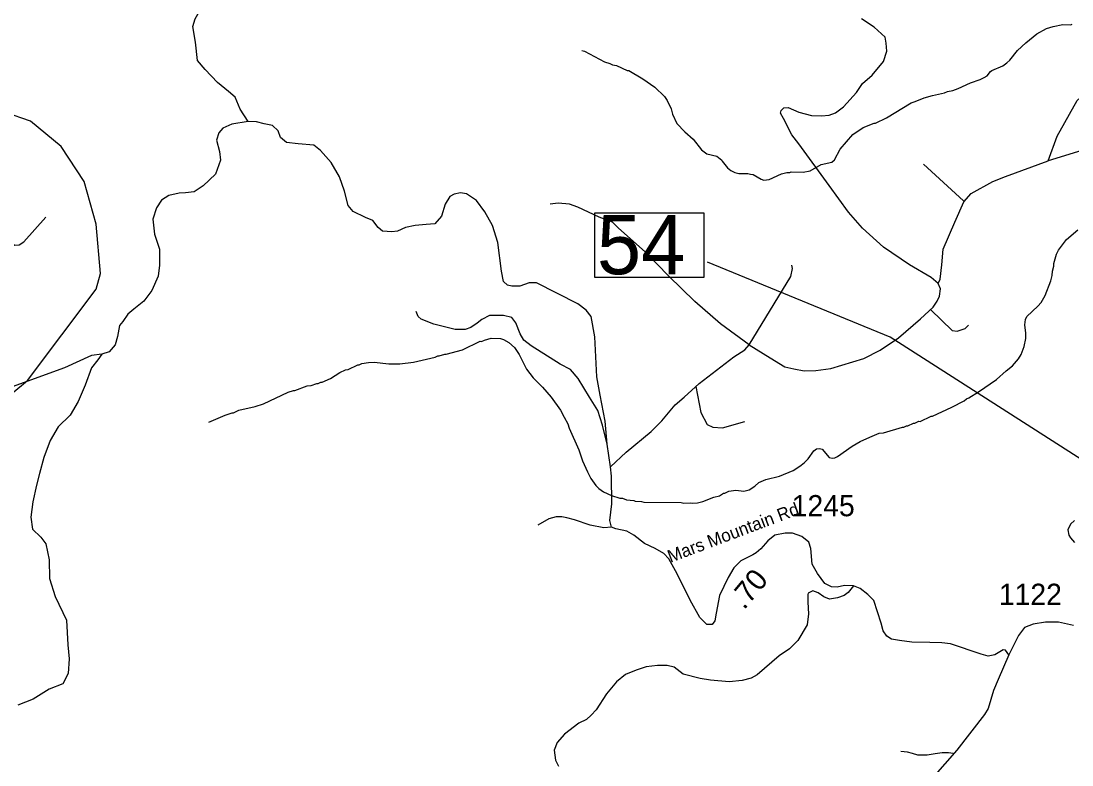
# Model space of a CAD drawing. Extents: x 1248089 to 1457196, y 820910 to 988753.
# Drawn here: x 1318874 to 1325079, y 852699 to 857095 of the extents above; entities that cross this region are included whole.
import ezdxf

# ---------------------------------------------------------------- set-up
doc = ezdxf.new("R2010")
doc.units = 0
for name, color, linetype in [('Exist Hydrographic Misc Water Feature', 7, 'Continuous'), ('Exist Road Non-System Type 51', 7, 'Continuous'), ('Exist Road Secondary Structure Standard Bridge Number Label', 7, 'Continuous'), ('Exist Road Secondary Type 51 Attributed', 7, 'Continuous'), ('Exist Road Secondary Type 51 Label', 7, 'Continuous'), ('Prop GRAU CAT1 Cell', 7, 'Continuous'), ('Prop Lane Lines', 7, 'Continuous')]:
    doc.layers.add(name, color=color, linetype=linetype)

msp = doc.modelspace()

# ---------------------------------------------------------------- linework, layer by layer
at = {"layer": 'Exist Hydrographic Misc Water Feature'}
for points in [[(1324152.8, 856618.6), (1324206.2, 856640.8), (1324254.5, 856655.6), (1324326.9, 856669.9), (1324343, 856677.6), (1324375.2, 856684.8), (1324407.5, 856696), (1324480.3, 856730.3), (1324536.6, 856749), (1324560.9, 856760.4), (1324577.1, 856770), (1324597.8, 856795.6), (1324605.9, 856801.4), (1324670.5, 856829.9), (1324694.9, 856847.3), (1324711.2, 856862.9), (1324756.6, 856919.8), (1324805.6, 856966.6), (1324870.8, 857019.1), (1324927.5, 857049.8), (1324967.8, 857062.9), (1325024.1, 857073.5), (1325072, 857072.4), (1325080.1, 857076.2)], [(1322184.3, 856920.1), (1322200.2, 856915.7), (1322318.8, 856853), (1322350.6, 856844.2), (1322366.4, 856835.9), (1322390.4, 856831.3), (1322453.6, 856801.8), (1322461.6, 856801.6), (1322544.6, 856753.7), (1322615.4, 856704.1), (1322672.2, 856648.7), (1322689.6, 856624.3), (1322712.6, 856575.8), (1322719.9, 856543.6), (1322746.6, 856489), (1322793.5, 856439.9), (1322842.5, 856396.8), (1322891.1, 856333.6), (1322922.6, 856310.9), (1322982.2, 856295.5), (1323011.8, 856272.8), (1323013.6, 856266.8), (1323044.7, 856228), (1323064.4, 856211.6), (1323088.1, 856199), (1323111.9, 856194.5), (1323166, 856193.2), (1323179.8, 856188.9), (1323195.8, 856188.5), (1323243.2, 856159.4), (1323259.1, 856155), (1323291.2, 856158.3), (1323364, 856192.6), (1323396.1, 856199.8), (1323412.1, 856199.4), (1323420.2, 856203.3), (1323492.2, 856201.6), (1323532.3, 856208.6), (1323597.2, 856247.1), (1323661.6, 856261.6), (1323675.8, 856275.3), (1323709.3, 856338.5), (1323785.2, 856424.7), (1323846.1, 856465.2), (1323910.8, 856491.7), (1323918.8, 856491.5), (1323983.5, 856522), (1324129.5, 856610.6), (1324152.8, 856618.6)], [(1318656.8, 854759.6), (1318911.8, 854971.1), (1319316.8, 855511.2), (1319343.8, 855602.6), (1319316.8, 855895.3), (1319247.8, 856146.2), (1319110.8, 856352.5), (1318930.8, 856503.8), (1318632.7, 856605)], [(1323941.3, 854659.3), (1323965.4, 854662.7), (1324078.1, 854696.1), (1324086.1, 854695.9), (1324102.3, 854703.5), (1324110.3, 854703.3), (1324142.6, 854718.5), (1324150.6, 854718.4), (1324174.9, 854729.8), (1324182.9, 854729.6), (1324247.6, 854760.1), (1324255.6, 854759.9), (1324368.8, 854813.2), (1324441.7, 854851.5), (1324456, 854863.2), (1324470.1, 854868.9), (1324526.9, 854903.5), (1324632.6, 854977), (1324689.7, 855027.7), (1324728.4, 855056.8), (1324763.3, 855099.9), (1324777.9, 855123.6), (1324797, 855171.1), (1324806.1, 855218.9), (1324806.8, 855250.9), (1324799.8, 855299.1), (1324804.5, 855330.9), (1324813, 855348.7), (1324876.4, 855409.3), (1324896.9, 855432.7), (1324919.8, 855472.2), (1324953.8, 855559.4), (1324962.5, 855591.2), (1324963.1, 855617.2), (1324971.8, 855647), (1324972.2, 855663), (1324987.4, 855716.6), (1324999.9, 855740.3), (1325047.3, 855803.2), (1325112.6, 855861.7)], [(1319982.4, 854724.1), (1320079.3, 854765.8), (1320119.7, 854780.9), (1320127.7, 854780.7), (1320160, 854795.9), (1320256.6, 854817.6), (1320304.9, 854832.5), (1320450.5, 854901.1), (1320482.8, 854912.3), (1320490.8, 854912.2), (1320563.4, 854938.5), (1320587.4, 854941.9), (1320619.6, 854953.1), (1320627.6, 854952.9), (1320643.8, 854960.6), (1320651.8, 854960.4), (1320700.3, 854983.2), (1320757.1, 855017.9), (1320789.5, 855033.1), (1320805.6, 855036.7), (1320862.2, 855063.4), (1320870.2, 855063.2), (1320886.3, 855070.8), (1320926.5, 855077.9), (1320958.6, 855079.1), (1321046.4, 855069.1), (1321110.3, 855069.6), (1321190.6, 855079.7), (1321319.3, 855108.7), (1321335.4, 855116.3), (1321343.4, 855116.1), (1321375.7, 855127.4), (1321383.7, 855127.2), (1321480.2, 855152.9), (1321585.4, 855202.4), (1321593.4, 855202.3), (1321609.5, 855209.9), (1321649.8, 855220.9), (1321705.8, 855219.6), (1321721.7, 855213.2), (1321753.3, 855194.5), (1321786.6, 855165.7), (1321815.7, 855125.1), (1321857.7, 855038.1), (1321898.5, 854987.1), (1321953.3, 854931.9), (1322003.9, 854872.7), (1322058.2, 854795.4), (1322080.7, 854754.6), (1322102.4, 854714.4), (1322109.9, 854690.3), (1322167, 854560.9), (1322189.5, 854496.4), (1322218, 854431.7), (1322239.1, 854391.2), (1322268.2, 854350.6), (1322285.8, 854332.2), (1322313.4, 854313.5), (1322360.8, 854292.4), (1322408.5, 854275.3), (1322424.5, 854274.9), (1322448.3, 854266.4), (1322492.2, 854261.3), (1322500.1, 854257.1), (1322538.1, 854256.3), (1322551.9, 854252), (1322772, 854250.8), (1322787.9, 854246.4), (1322827.9, 854247.5), (1322835.8, 854245.3), (1322867.9, 854248.5), (1322900.1, 854255.8), (1322964.7, 854282.2), (1322996.9, 854289.5), (1323021.2, 854304.9), (1323029.2, 854304.8), (1323053.5, 854316.2), (1323093.6, 854323.2), (1323141.6, 854318.1), (1323173.7, 854325.4), (1323206.2, 854346.6), (1323230.7, 854368), (1323271.1, 854387), (1323351.5, 854405.2), (1323432.3, 854439.3), (1323472.8, 854464.3), (1323497.3, 854483.7), (1323521.8, 854509.1), (1323555, 854556.4), (1323571.3, 854568), (1323587.3, 854569.6), (1323603.1, 854565.2), (1323646.1, 854516.3), (1323662, 854511.9), (1323678, 854513.5), (1323694.2, 854521.1), (1323781.5, 854583.1), (1323828.2, 854610), (1323884.8, 854636.6), (1323941.3, 854659.3)]]:
    msp.add_lwpolyline(points, dxfattribs=at)
at = {"layer": 'Exist Road Non-System Type 51'}
msp.add_line((1324438, 856032.4), (1324201.2, 856249.4), dxfattribs=at)
for points in [[(1320215.8, 856501.4), (1320167.2, 856574.7), (1320137.4, 856645.1), (1320099.5, 856677.6), (1320034.6, 856731.8), (1319961.5, 856807.6), (1319915.5, 856861.8), (1319904.7, 856970.1), (1319888.5, 857062.2), (1319902, 857108.2), (1319934.5, 857162.4), (1319948, 857224.7), (1319956.1, 857295.1), (1319939.9, 857370.9), (1319902, 857398), (1319856, 857406.1), (1319804.6, 857406.1), (1319753.1, 857403.4), (1319718, 857422.4), (1319625.9, 857528)], [(1324288.6, 855544), (1324248.1, 855579.7), (1324119.9, 855654.5), (1323965, 855758.8), (1323842.1, 855871), (1323759.3, 855964.6), (1323644.5, 856122.3), (1323465.5, 856368.2), (1323425.4, 856421.6), (1323374.7, 856517.9), (1323358.7, 856549.9), (1323361.3, 856566), (1323377.4, 856582), (1323404.1, 856584.7), (1323465.5, 856555.3), (1323540.3, 856536.6), (1323599.1, 856533.9), (1323644.5, 856539.3), (1323681.9, 856552.6), (1323729.9, 856587.4), (1323807.4, 856672.9), (1323842.1, 856726.4), (1323898.2, 856774.5), (1323965, 856854.7), (1323986.4, 856916.1), (1323981, 856964.3), (1323975.7, 856999), (1323911.6, 857057.8), (1323837, 857107)], [(1324938.4, 856267.8), (1324991.8, 856414.7), (1325108.6, 856625), (1325165.3, 856675.1), (1325358.8, 856775.2), (1325412.2, 856798.6), (1325475.5, 856785.3), (1325462.2, 856681.8), (1325422.2, 856581.6), (1325305.4, 856471.4)], [(1320215.8, 856501.4), (1320119.2, 856485.3), (1320065.5, 856461.1), (1320041.3, 856434.2), (1320027.9, 856391.3), (1320046.7, 856324.1), (1320052.1, 856273.1), (1320022.5, 856189.8), (1319950.1, 856120), (1319896.4, 856085.1), (1319845.4, 856079.7), (1319807.8, 856077), (1319746.1, 856063.6), (1319703.1, 856036.7), (1319673.6, 855991), (1319652.1, 855923.9), (1319662.9, 855835.2), (1319692.4, 855746.6), (1319692.4, 855652.6), (1319684.3, 855588.1), (1319646.8, 855502.2), (1319598.5, 855440.4), (1319539.4, 855392), (1319504.5, 855362.5), (1319475, 855319.5), (1319456.2, 855295.4), (1319442.8, 855230.9), (1319429.4, 855182.5), (1319394.5, 855139.6), (1319351.5, 855126.1)], [(1320983.4, 855875.5), (1320951.2, 855915.8), (1320908.3, 855934.6), (1320835.8, 855969.6), (1320806.3, 856004.5), (1320784.8, 856090.4), (1320755.3, 856173.7), (1320704.3, 856259.6), (1320642.6, 856329.5), (1320602.3, 856361.7), (1320511, 856369.8), (1320441.3, 856377.8), (1320406.4, 856407.4), (1320392.9, 856445), (1320358, 856477.2), (1320309.7, 856488), (1320264.1, 856498.7), (1320215.8, 856501.4)], [(1325305.4, 856471.4), (1325178.6, 856347.9), (1325111.9, 856321.2), (1324938.4, 856267.8)], [(1324288.6, 855544), (1324301.5, 855569.6), (1324309.5, 855655.1), (1324317.5, 855746), (1324386.9, 855906.4), (1324440.4, 856026.7), (1324483.1, 856074.8), (1324611.3, 856147), (1324686.1, 856176.4), (1324938.4, 856267.8)], [(1322334.6, 854595.3), (1322322.8, 854731.3), (1322293.3, 854884.4), (1322274.5, 854991.8), (1322261.1, 855228.2), (1322239.6, 855349.1), (1322210.1, 855386.7), (1322161.7, 855424.3), (1321917.5, 855547.8), (1321874.6, 855547.8), (1321818.2, 855529), (1321772.6, 855529), (1321745.7, 855534.4), (1321721.6, 855555.9), (1321710.8, 855617.7), (1321689.4, 855786.9), (1321657.1, 855886.3), (1321611.5, 855966.9), (1321563.2, 856034), (1321504.1, 856074.3), (1321469.3, 856079.7), (1321431.7, 856071.6), (1321404.8, 856058.2), (1321378, 856012.5), (1321356.5, 855942.7), (1321316.3, 855897), (1321265.3, 855891.7), (1321200.8, 855886.3), (1321144.5, 855875.5), (1321096.2, 855854.1), (1321064, 855848.7), (1321007.6, 855854.1), (1320983.4, 855875.5)], [(1323173.3, 855180.7), (1323003.9, 855306.2), (1322851.6, 855437.1), (1322696.7, 855589.5), (1322560.5, 855728.5), (1322400.2, 855872.8), (1322366.5, 855906.3), (1322286.4, 855935.7), (1322160.9, 855994.6), (1322112.8, 856013.3), (1322046, 856018.6), (1321997.9, 856013.3)], [(1318369.2, 855201.3), (1318359.4, 855296.4), (1318356.7, 855320.8), (1318359.4, 855353.3), (1318378.4, 855375), (1318413.5, 855418.3), (1318419, 855458.9), (1318419, 855529.3), (1318394.6, 855640.4), (1318383.8, 855743.3), (1318386.5, 855827.2), (1318413.5, 855851.6), (1318486.6, 855889.5), (1318532.6, 855894.9), (1318570.5, 855900.4), (1318624.6, 855892.2), (1318640.9, 855881.4), (1318703.1, 855859.7), (1318751.8, 855829.9), (1318822.2, 855781.2), (1318838.4, 855770.4), (1318862.8, 855773.1), (1318889.8, 855789.3), (1319019.7, 855935.6)], [(1323173.3, 855180.7), (1323418.3, 855586), (1323428.3, 855632.8), (1323424.9, 855652.8)], [(1323173.3, 855180.7), (1323297.7, 855105.7), (1323383.1, 855052.2), (1323436.6, 855038.9), (1323498, 855028.2), (1323567.4, 855030.8), (1323655.6, 855041.5), (1323850.6, 855100.3), (1323946.7, 855151.1), (1324053.6, 855223.3), (1324184.5, 855335.6), (1324259.2, 855405), (1324283.3, 855439.8), (1324296.6, 855469.2), (1324302, 855512), (1324288.6, 855544)], [(1322353.8, 854461.6), (1322334.6, 854595.3), (1322307.8, 854707.6), (1322278.5, 854793.1), (1322230.4, 854873.3), (1322163.6, 854982.9), (1322118.2, 855036.4), (1322056.8, 855068.4), (1321885.8, 855175.4), (1321843.1, 855210.1), (1321821.7, 855247.5), (1321795, 855311.7), (1321771, 855343.8), (1321722.9, 855354.5), (1321640.1, 855354.5), (1321594.7, 855330.4), (1321568, 855309), (1321530.6, 855285), (1321495.9, 855271.6), (1321437.1, 855271.6), (1321311.6, 855303.7), (1321236.8, 855333.1), (1321218.1, 855349.1), (1321207.4, 855378.5)], [(1324244.7, 855388.9), (1324371.4, 855265.4), (1324401.5, 855262), (1324448.2, 855278.7), (1324468.2, 855298.7)], [(1319351.5, 855126.1), (1319289.8, 855118.1), (1319131.4, 855045.5), (1318822.8, 854932.7), (1318653.7, 854887.1), (1318573.1, 854876.3), (1318519.5, 854879), (1318495.3, 854895.1), (1318481.9, 854930), (1318492.6, 854983.8), (1318500.7, 855069.7), (1318487.3, 855120.8), (1318441.6, 855161), (1318369.2, 855201.3)], [(1319351.5, 855126.1), (1319327.4, 855093.9), (1319289.8, 855045.6), (1319252.2, 854943.5), (1319212, 854846.8), (1319163.6, 854766.2), (1319093.9, 854696.4), (1319045.5, 854615.8), (1319008, 854516.4), (1318983.8, 854422.4), (1318965, 854352.6), (1318943.5, 854253.2), (1318932.8, 854164.5), (1318940.9, 854092), (1318991.9, 854046.3), (1319021.4, 854006.1), (1319040.2, 853912), (1319042.9, 853801.9), (1319075.1, 853694.5), (1319142.2, 853554.8), (1319150.2, 853409.7), (1319158.3, 853326.5), (1319152.9, 853240.5), (1319120.7, 853178.7), (1319040.2, 853146.5), (1318946.2, 853087.4), (1318855, 853052.5)], [(1322353.8, 854461.6), (1322446.7, 854547.2), (1322593.6, 854670.2), (1322657.8, 854731.7), (1322735.2, 854827.9), (1322788.6, 854873.3), (1322876.8, 854953.5), (1323082.4, 855111.2), (1323146.5, 855151.3), (1323173.3, 855180.7)], [(1322857.8, 854935), (1322887.8, 854781.5), (1322924.5, 854711.4), (1322957.9, 854694.7), (1323014.6, 854691.3), (1323148, 854728)], [(1322361, 854104.8), (1322315, 854099.7), (1322234.3, 854117), (1322142.1, 854148.7), (1322096, 854160.2), (1322067.1, 854166), (1322032.6, 854166), (1321989.3, 854154.5), (1321925.9, 854117)], [(1323788.9, 853757.5), (1323756.9, 853719), (1323734.3, 853700.5), (1323695.3, 853686.1), (1323648.1, 853679.9), (1323613.1, 853692.3), (1323580.3, 853716.9), (1323549.5, 853729.2), (1323520.7, 853714.9), (1323518.7, 853706.6), (1323518.7, 853661.4), (1323522.8, 853591.5), (1323514.5, 853527.8), (1323461.1, 853435.3), (1323411.9, 853386), (1323350.2, 853344.9), (1323220.8, 853231.8), (1323183.9, 853213.3), (1323132.5, 853198.9), (1323054.5, 853190.7), (1322945.6, 853201), (1322884, 853211.3), (1322783.3, 853235.9), (1322729.9, 853277.1), (1322688.9, 853287.3), (1322631.3, 853287.3), (1322565.6, 853279.1), (1322506.1, 853260.6), (1322442.4, 853233.9), (1322389, 853190.7), (1322331.5, 853120.8), (1322269.2, 853025.2), (1322240.5, 852994.3), (1322211.7, 852967.6), (1322166.5, 852947), (1322082.3, 852881.3), (1322039.2, 852831.9), (1322020.7, 852786.7), (1322028.9, 852727.1), (1322047.4, 852692.2)], [(1324377.4, 852766.4), (1324350.6, 852770.5), (1324313, 852770.5), (1324270.1, 852765.1), (1324223.1, 852757), (1324169.4, 852758.4), (1324137.2, 852766.4), (1324107.7, 852775.8), (1324067.4, 852778.5)]]:
    msp.add_lwpolyline(points, dxfattribs=at)
at = {"layer": 'Exist Road Secondary Structure Standard Bridge Number Label'}
msp.add_lwpolyline([(1322261.9, 855961.1), (1322906.1, 855961.1), (1322906.1, 855578.8), (1322261.9, 855578.8)], close=True, dxfattribs=at)
msp.add_lwpolyline([(1325306.9, 854394.1), (1324006.3, 855227.2), (1322926.7, 855669.3)], dxfattribs=at)
at = {"layer": 'Exist Road Secondary Type 51 Attributed'}
for points in [[(1324705.7, 853350.9), (1324686.9, 853378.4), (1324672.3, 853380), (1324653, 853368.7), (1324624, 853349.3), (1324583.7, 853342.9), (1324543.4, 853354.2), (1324361.2, 853415.5), (1324311.2, 853421.9), (1324240.3, 853423.6), (1324132.3, 853425.2), (1324061.4, 853434.8), (1324013, 853442.9), (1323985.6, 853460.7), (1323964.6, 853492.9), (1323951.7, 853536.5), (1323909.8, 853672), (1323874.4, 853705.9), (1323827.6, 853743), (1323788.9, 853757.5), (1323735.7, 853759.1), (1323692.2, 853749.5), (1323658.3, 853752.7), (1323619.6, 853772), (1323576.1, 853831.7), (1323543.9, 853885), (1323537.1, 853979.4), (1323524.2, 854016.5), (1323483.9, 854048.8), (1323429, 854068.2), (1323385.5, 854068.2), (1323324.3, 854056.9), (1323282.3, 854024.6), (1323242, 853976.2), (1323214.6, 853953.6), (1323195.3, 853940.7), (1323124.4, 853905.2), (1323082.4, 853864.9), (1323048.6, 853806.8), (1322997, 853700.3), (1322977.7, 853597.1), (1322969.6, 853551.9), (1322955.1, 853529.3), (1322922.8, 853529.3), (1322880.9, 853571.2), (1322824.5, 853672.9), (1322748.7, 853829.4), (1322697.9, 853917.7), (1322668.9, 853948.3), (1322618.9, 853979), (1322554.5, 854008), (1322491.6, 854058), (1322451.3, 854080.6), (1322385.2, 854095.1), (1322361, 854104.8), (1322349.7, 854143.5), (1322362.6, 854241.9), (1322359.4, 854404.9), (1322353.8, 854461.6)], [(1325094, 854144), (1325069.5, 854121.4), (1325055, 854088.7), (1325059.6, 854056.9), (1325069.5, 854041.5), (1325094, 854014.3)], [(1325087.2, 853523.3), (1325051.8, 853531.5), (1324999.2, 853543.3), (1324922.1, 853543.3), (1324849.5, 853531.5), (1324799.3, 853512.5), (1324763.6, 853463.6), (1324705.7, 853350.9)], [(1324705.7, 853350.9), (1324643, 853204.8), (1324615.8, 853139.5), (1324583.1, 853032.4), (1324563.2, 852997), (1324398.9, 852787.4), (1324187, 852545.5)]]:
    msp.add_lwpolyline(points, dxfattribs=at)

# ---------------------------------------------------------------- texts
at = {"layer": 'Exist Road Secondary Structure Standard Bridge Number Label'}
msp.add_text('54', height=350, dxfattribs=at).set_placement((1322274.5, 855598.6))
at = {"layer": 'Exist Road Secondary Type 51 Label'}
msp.add_text('Mars Mountain Rd', height=75, rotation=20.64581, dxfattribs=at).set_placement((1322707.7, 853893.3))
at = {"layer": 'Prop GRAU CAT1 Cell'}
msp.add_text('.70', height=125, rotation=50.21669, dxfattribs=at).set_placement((1323143, 853611.8))
at = {"layer": 'Prop Lane Lines'}
for s, p in [('1245', (1323424.3, 854169)), ('1122', (1324647.2, 853645.4))]:
    msp.add_text(s, height=125, dxfattribs=at).set_placement(p)

doc.saveas('drawing.dxf')
